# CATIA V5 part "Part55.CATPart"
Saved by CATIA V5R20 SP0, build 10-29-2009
Part number: IA 2275SF
Revision: ANY
Definition: UNKNOWN
Nomenclature: IA 2275SF
Source: Unknown
Bounding box of the stored display mesh (mm): x -1.102 to 1.102, y -0.001 to 7.75, z -1.102 to 1.102
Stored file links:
  C:\Users\Utente\Desktop\IO LAVORO\3D X SITO CF\CUMSA\3D files FA\FA 042204-21\Part55.CATPart

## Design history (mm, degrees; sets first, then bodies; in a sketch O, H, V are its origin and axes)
Body1 "Cortar-Extruir2" (main body)
  Solid1: solid without history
